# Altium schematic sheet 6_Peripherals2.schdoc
size 309 x 223 mm; Symbol: Sheet-Symbol_A4; Device: Sheet-Symbol_A4; @Project Name: Actuator Module; @Page Count: 6; @Update Date: 2025-01-18; @Create Date: 2025-01-01; @Schematic Name: Schematic-A_2; @Page No: 6; @Page Name: Peripherals2; Company: UA Nasa Robotics; Reviewed: None; Version: 1.0; Page Size: A4; Part Number: AA; Drawn: Eli B; @Board Name: BaseModule; @Create Time: 18:08:48; @Update Time: 19:01:51
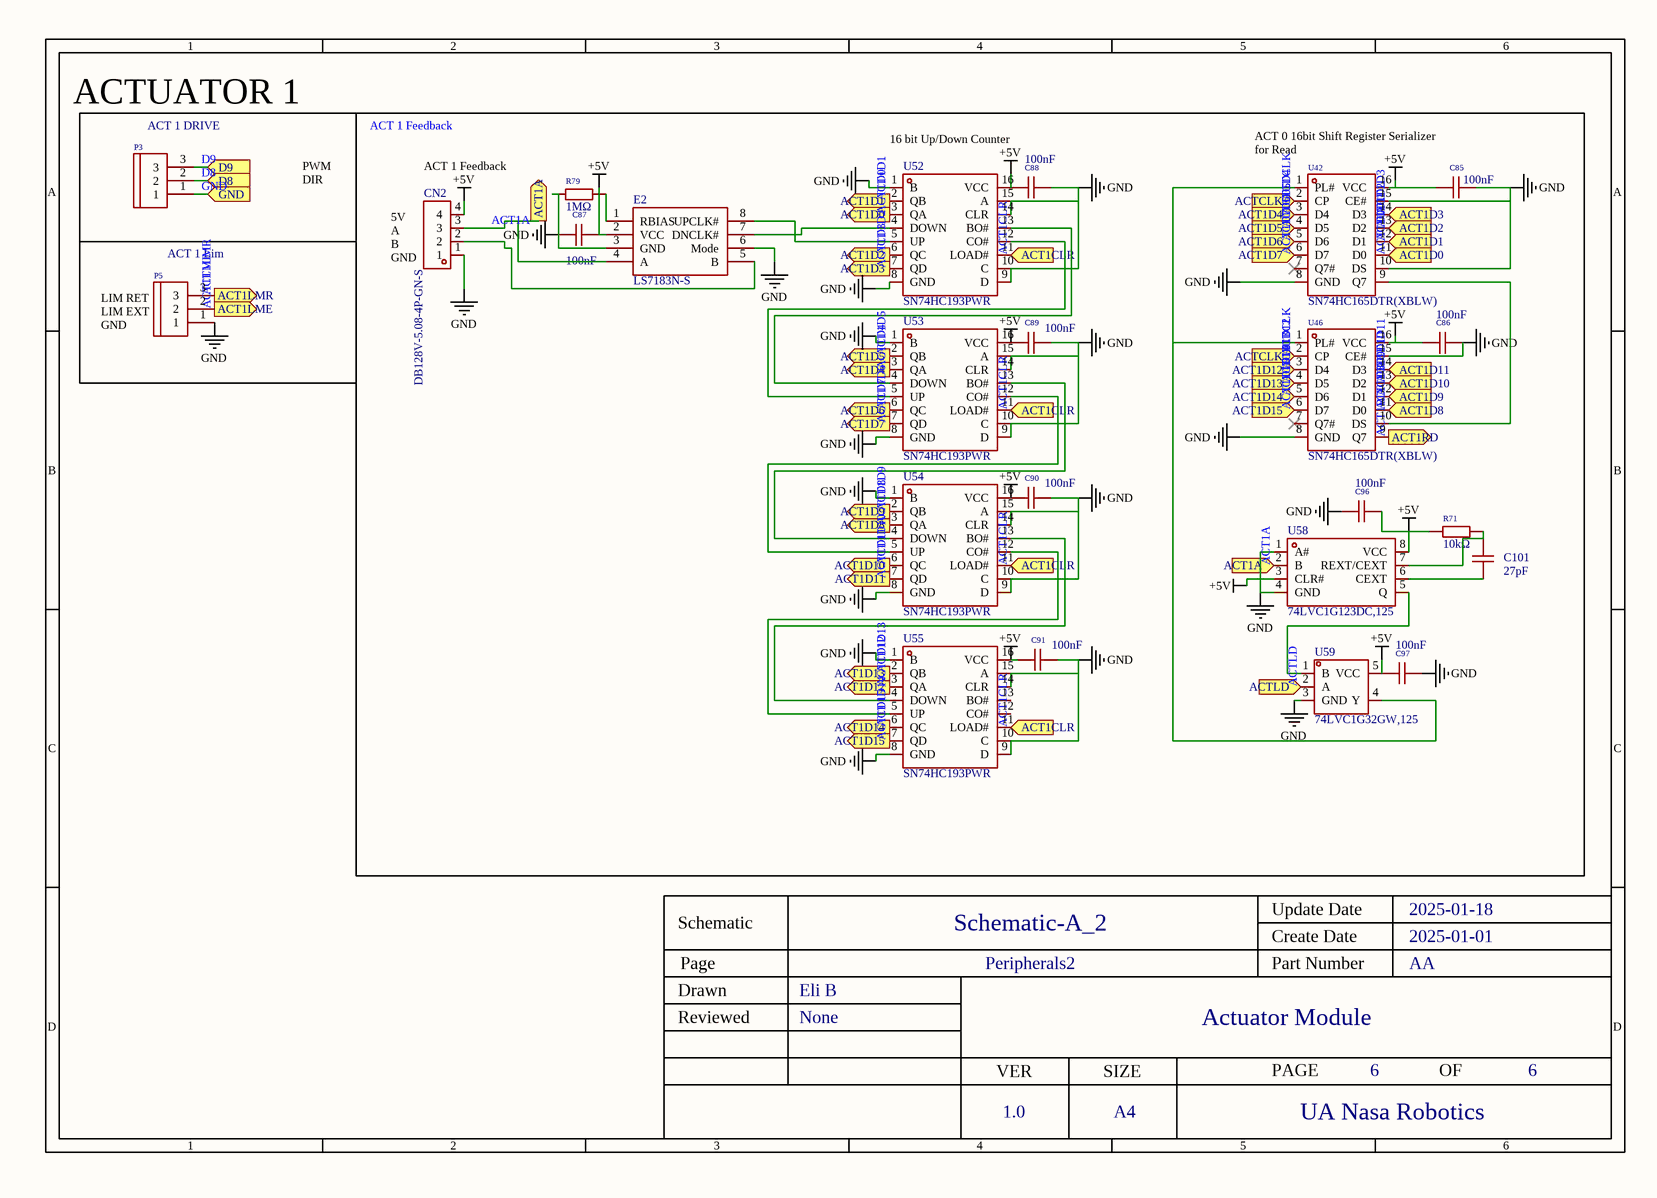
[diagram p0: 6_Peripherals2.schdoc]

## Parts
C85  100nF  [C0805]
C86  100nF  [C0805]
C87  100nF  [C0805]
C88  100nF  [C0805]
C89  100nF  [C0805]
C90  100nF  [C0805]
C91  100nF  [C0805]
C96  100nF  [C0805]
C97  100nF  [C0805]
C101  27pF  [C0603]
CN2  DB128V-5.08-4P-GN-S  [CONN-TH_4P-P5.08_DIBO_DB128V-5.08]
E2  LS7183N-S  [SOIC-8_L5.0-W4.0-P1.27-LS6.0-TL]
P3  ACT 1 DRIVE  [CONN-TH_3P-P5.00_WJ500V-5.08-3P]
P5  ACT 1 Lim  [CONN-TH_3P-P5.00_WJ500V-5.08-3P]
R71  10kΩ  [R0805]
R79  1MΩ  [R1206]
U42  SN74HC165DTR(XBLW)  [SOP-16_L9.9-W3.9-P1.27-LS6.0-BL]
U46  SN74HC165DTR(XBLW)  [SOP-16_L9.9-W3.9-P1.27-LS6.0-BL]
U52  SN74HC193PWR  [TSSOP-16_L5.0-W4.4-P0.65-LS6.4-BL]
U53  SN74HC193PWR  [TSSOP-16_L5.0-W4.4-P0.65-LS6.4-BL]
U54  SN74HC193PWR  [TSSOP-16_L5.0-W4.4-P0.65-LS6.4-BL]
U55  SN74HC193PWR  [TSSOP-16_L5.0-W4.4-P0.65-LS6.4-BL]
U58  74LVC1G123DC,125  [VSSOP-8_L2.4-W2.1-P0.50-LS3.2-BR]
U59  74LVC1G32GW,125  [SOT-353_L2.2-W1.4-P0.65-LS2.4-BR]

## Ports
ACT1A (in), ACT1A (out), ACT1CLR (in), ACT1D0 (in), ACT1D0 (out), ACT1D1 (in), ACT1D1 (out), ACT1D2 (in), ACT1D2 (out), ACT1D3 (in), ACT1D3 (out), ACT1D4 (in), ACT1D4 (out), ACT1D5 (in), ACT1D5 (out), ACT1D6 (in), ACT1D6 (out), ACT1D7 (in), ACT1D7 (out), ACT1D8 (in), ACT1D8 (out), ACT1D9 (in), ACT1D9 (out), ACT1D10 (in), ACT1D10 (out), ACT1D11 (in), ACT1D11 (out), ACT1D12 (in), ACT1D12 (out), ACT1D13 (in), ACT1D13 (out), ACT1D14 (in), ACT1D14 (out), ACT1D15 (in), ACT1D15 (out), ACT1LME (out), ACT1LMR (out), ACT1RD (out), ACTCLK (in), ACTLD (in), D8 (in), D9 (in), GND (in)

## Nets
+5V: C85.1 C86.2 C87.2 C88.1 C89.1 C90.1 C91.1 C96.1 C97.2 CN2.4 E2.2(VCC) R71.1 U42.16(VCC) U46.16(VCC) U52.16(VCC) U53.16(VCC) U54.16(VCC) U55.16(VCC) U58.3(CLR#) U58.8(VCC) U59.5(VCC)
GND: C85.2 C86.1 C87.1 C88.2 C89.2 C90.2 C91.2 C96.2 C97.1 CN2.1 E2.3(GND) E2.6(Mode) P3.1 P5.1 R79.1 U42.8(GND) U42.10(DS) U42.15(CE#) U46.8(GND) U46.15(CE#) U52.1(B) U52.8(GND) U52.9(D) U52.10(C) U52.14(CLR) U52.15(A) U53.1(B) U53.8(GND) U53.9(D) U53.10(C) U53.14(CLR) U53.15(A) U54.1(B) U54.8(GND) U54.9(D) U54.10(C) U54.14(CLR) U54.15(A) U55.1(B) U55.8(GND) U55.9(D) U55.10(C) U55.14(CLR) U55.15(A) U58.1(A#) U58.4(GND) U59.3(GND) ; port GND
ACT1A: CN2.3 E2.4(A) U58.2(B) ; port ACT1A
ACT1CLR: U52.11(LOAD#) U53.11(LOAD#) U54.11(LOAD#) U55.11(LOAD#) ; port ACT1CLR
ACT1D0: U42.11(D0) U52.3(QA) ; port ACT1D0
ACT1D1: U42.12(D1) U52.2(QB) ; port ACT1D1
ACT1D2: U42.13(D2) U52.6(QC) ; port ACT1D2
ACT1D3: U42.14(D3) U52.7(QD) ; port ACT1D3
ACT1D4: U42.3(D4) U53.3(QA) ; port ACT1D4
ACT1D5: U42.4(D5) U53.2(QB) ; port ACT1D5
ACT1D6: U42.5(D6) U53.6(QC) ; port ACT1D6
ACT1D7: U42.6(D7) U53.7(QD) ; port ACT1D7
ACT1D8: U46.11(D0) U54.3(QA) ; port ACT1D8
ACT1D9: U46.12(D1) U54.2(QB) ; port ACT1D9
ACT1D10: U46.13(D2) U54.6(QC) ; port ACT1D10
ACT1D11: U46.14(D3) U54.7(QD) ; port ACT1D11
ACT1D12: U46.3(D4) U55.3(QA) ; port ACT1D12
ACT1D13: U46.4(D5) U55.2(QB) ; port ACT1D13
ACT1D14: U46.5(D6) U55.6(QC) ; port ACT1D14
ACT1D15: U46.6(D7) U55.7(QD) ; port ACT1D15
ACT1LME: P5.2 ; port ACT1LME
ACT1LMR: P5.3 ; port ACT1LMR
ACT1RD: U46.9(Q7) ; port ACT1RD
ACTCLK: U42.2(CP) U46.2(CP) ; port ACTCLK
ACTLD: U59.2(A) ; port ACTLD
D8: P3.2 ; port D8
D9: P3.3 ; port D9
NetC101_1: C101.1 U58.6(CEXT)
NetC101_2: C101.2 R71.2 U58.7(REXT/CEXT)
NetCN2_2: CN2.2 E2.5(B)
NetE2_1: E2.1(RBIAS) R79.2
NetE2_7: E2.7(DNCLK#) U52.4(DOWN)
NetE2_8: E2.8(UPCLK#) U52.5(UP)
NetU42_1: U42.1(PL#) U46.1(PL#) U59.4(Y)
NetU42_9: U42.9(Q7) U46.10(DS)
NetU52_12: U52.12(CO#) U53.5(UP)
NetU52_13: U52.13(BO#) U53.4(DOWN)
NetU53_12: U53.12(CO#) U54.5(UP)
NetU53_13: U53.13(BO#) U54.4(DOWN)
NetU54_12: U54.12(CO#) U55.5(UP)
NetU54_13: U54.13(BO#) U55.4(DOWN)
NetU58_5: U58.5(Q) U59.1(B)

Not connected (* = marked no-connect by the designer): U42 7(Q7#)*; U46 7(Q7#)*; U55 12(CO#) 13(BO#)

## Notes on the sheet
- ACTUATOR 1
- ACT 1 Feedback
- 16 bit Up/Down Counter
- (near U42) ACT 0 16bit Shift Register Serializer
  for Read
- PWM
- DIR
- (near CN2) 5V
  A
  B
  GND
- (near P5) LIM RET
  LIM EXT
  GND

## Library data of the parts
C85-C91 C96 C97 = 0805B104K500NT: Manufacturer: FH(风华); Add into BOM: yes; Tolerance: ±10%
C101 = CC0603JRNPO9BN270: Manufacturer: YAGEO(国巨); Add into BOM: yes; Tolerance: ±5%
CN2 = DB128V-5.08-4P-GN-S: Manufacturer: DORABO(地博电气); Add into BOM: yes; Structure: 1x4P; Pitch: 5.08mm; Current Rating (Max): 20A; Voltage Rating (Max): 300V; Wire Gauge - AWG: 12~30; Wire Gauge - mm2: 2.5; Number of PINs Per Row: 4
E2 = LS7183N-S: Add into BOM: yes
P3 P5 = WJ500V-5.08-3P: Manufacturer: KANGNEX(康奈克斯电气); Symbol: WJ500V-5.08-3P-14-00A; Add into BOM: yes; Structure: 1x3P; Pitch: 5.08mm; Current Rating (Max): 18A; Voltage Rating (Max): 250V; Wire Gauge - AWG: 14~30; Wire Gauge - mm2: 2.5; Number of PINs Per Row: 3
R71 = 0805W8F1002T5E: Manufacturer: UNI-ROYAL(厚声); Add into BOM: yes; Tolerance: ±1%; Temperature Coefficient: ±100ppm/℃
R79 = 1206W4F1004T5E: Manufacturer: UNI-ROYAL(厚声); Add into BOM: yes; Tolerance: ±1%; Temperature Coefficient: ±100ppm/℃
U42 U46 = SN74HC165DTR(XBLW): Manufacturer: XBLW(芯伯乐); Add into BOM: yes; Supply Voltage: 2V~6V
U52-U55 = SN74HC193PWR: Manufacturer: TI(德州仪器); Add into BOM: yes; Logic Type: Binary Counter; Direction: 向上计数器；向下计数器; Supply Voltage: 2V~6V; Number of Elements: 1; Number of Bits per Element: 4; Trigger Type: Positive Edge; Reset Style: 异步; Timing mode: Synchronous; Count Rate: 24MHz
U58 = 74LVC1G123DC,125: Manufacturer: Nexperia(安世); Add into BOM: yes; Logic Gate Type: Monostable; Supply Voltage: 1.65V~5.5V; Number Of Channels: 1; Input Type: Schmitt Trigger; Propagation Delay: 5.3ns; Sink Current: 32mA; Logic Family: 74LVC
U59 = 74LVC1G32GW,125: Manufacturer: Nexperia(安世); Add into BOM: yes; Logic Gate Type: ORGate; Number of Channels: 1; Supply Voltage: 1.65V~5.5V; Quiescent Current (Max): 4uA; Sink Current: 32mA; High Level Range (VIH): 1.7V~2V; Low Level Range (VIL): 700mV~800mV; Propagation Delay Time: 4ns@5V,50pF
